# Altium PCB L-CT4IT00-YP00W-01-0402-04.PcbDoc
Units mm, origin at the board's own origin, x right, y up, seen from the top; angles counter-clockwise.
Board outline 187.63 x 116.13 mm, 6 copper layers (Top Layer, (Inserted) GND1, (Inserted) Signal3, (Inserted) Siganl4, (Inserted) GND5, Bottom Layer); 12 components, 0 nets, 14 pads, 0 vias.
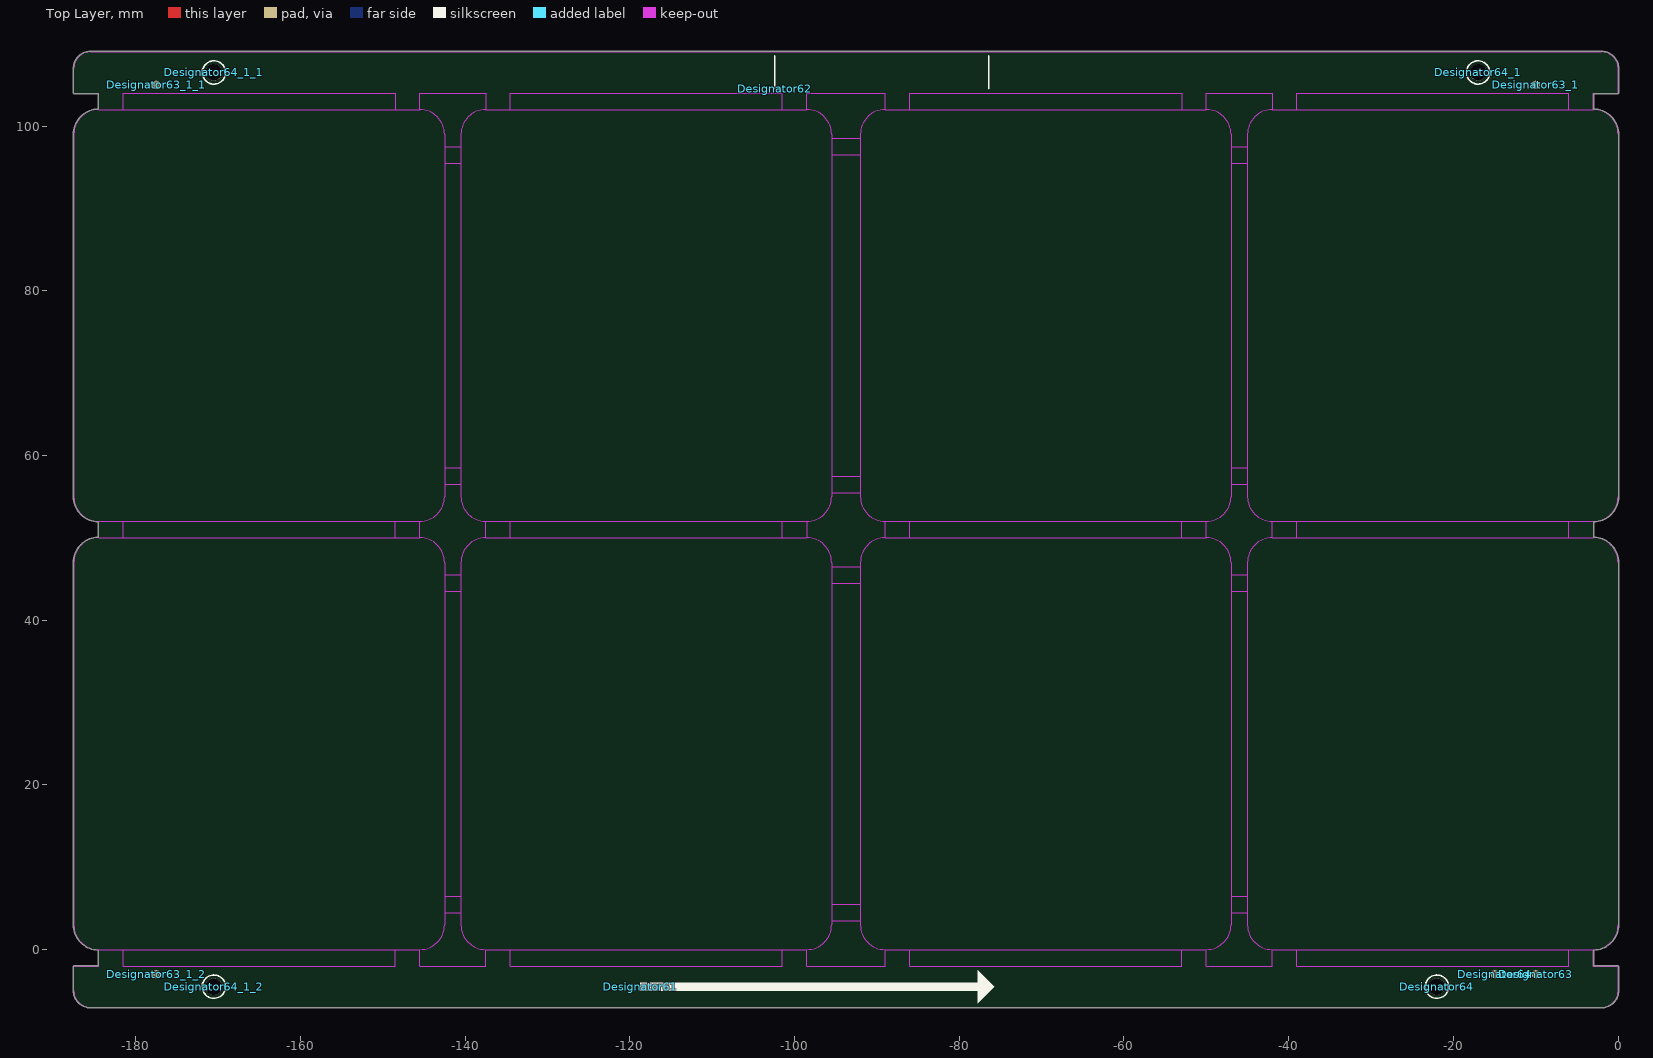
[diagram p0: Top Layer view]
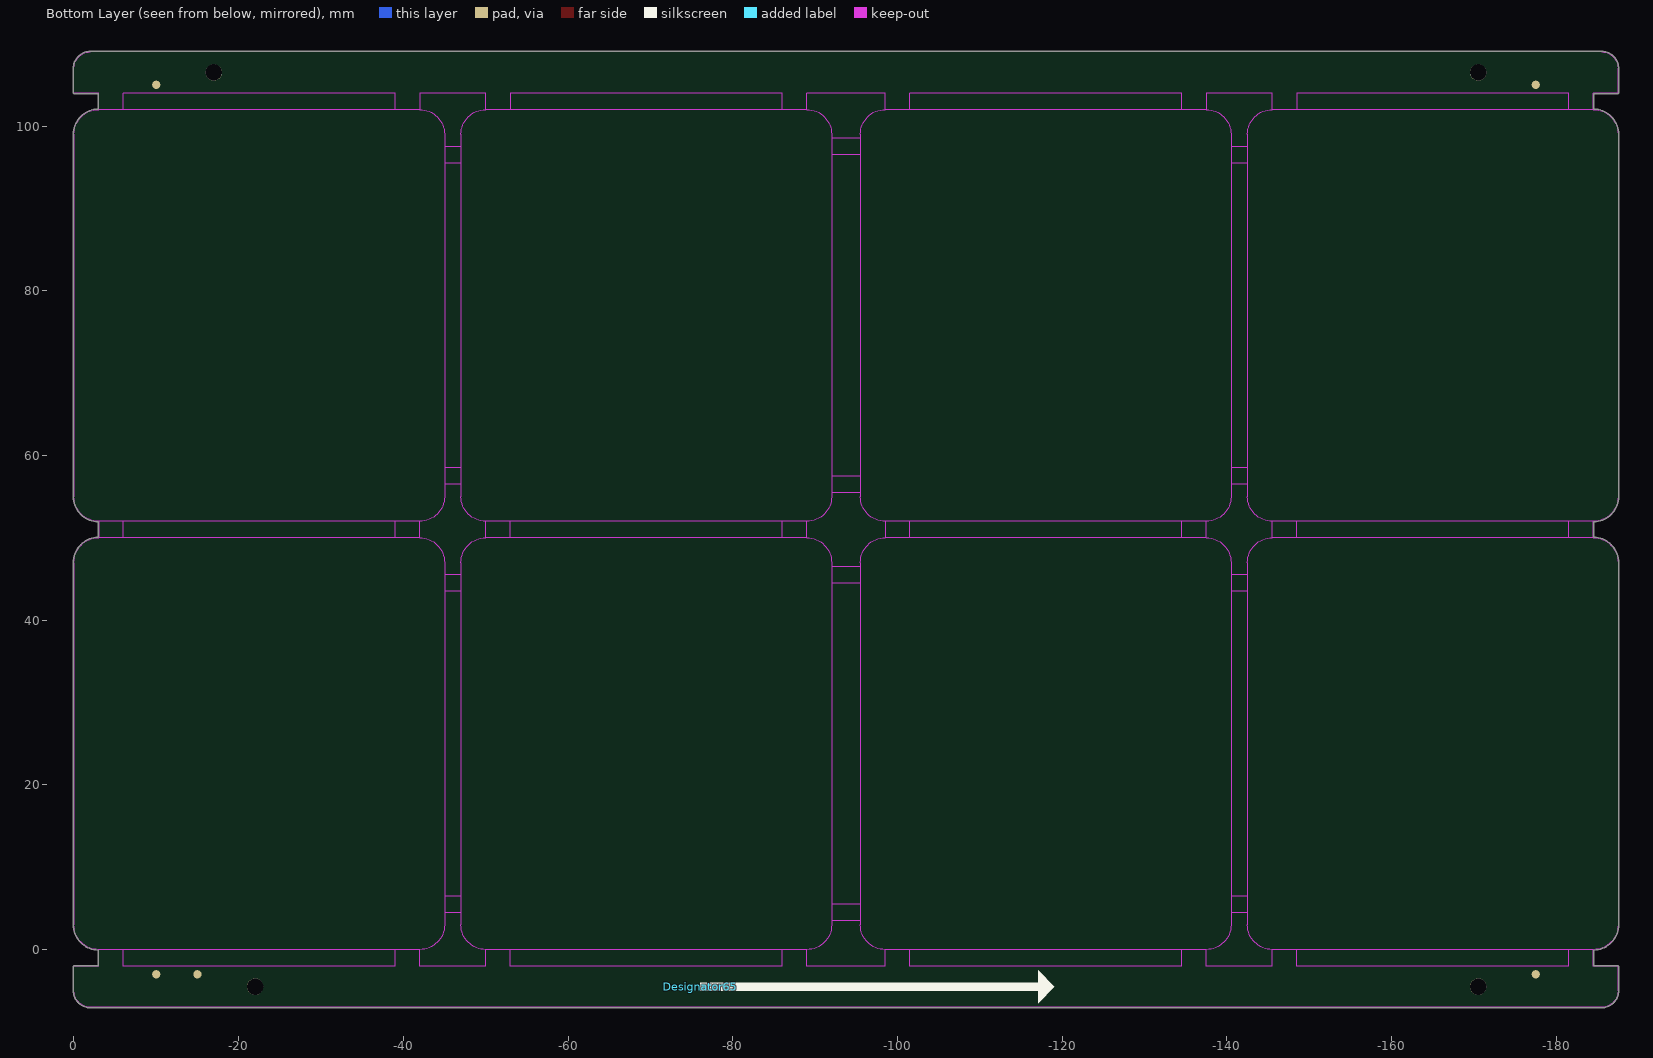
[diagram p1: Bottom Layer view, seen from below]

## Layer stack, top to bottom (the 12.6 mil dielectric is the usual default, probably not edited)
Top Solder: solder mask 0.0102, Solder Resist, Dk 3.5
Top Layer: signal copper 0.0356
(Inserted) Dielectric 5: prepreg 0.32, FR-4, Dk 4.8
(Inserted) GND1: signal copper 0.0356
(Inserted) Dielectric 4: prepreg 0.32, FR-4, Dk 4.8
(Inserted) Signal3: signal copper 0.0356
(Inserted) Dielectric 3: prepreg 0.32, FR-4, Dk 4.8
(Inserted) Siganl4: signal copper 0.0356
(Inserted) Dielectric 2: prepreg 0.32, FR-4, Dk 4.8
(Inserted) GND5: signal copper 0.0356
Dielectric 1: dielectric 0.32, FR-4, Dk 4.8
Bottom Layer: signal copper 0.0356
Bottom Solder: solder mask 0.0102, Solder Resist, Dk 3.5

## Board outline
-187.564,-5 -187.564,-2 -187.5,-1.936 -184.564,-1.936 -184.564,-0.063 cw(c-184.5,3) -187.564,3 -187.564,47 cw(c-184.5,47) -184.564,50.063 -184.564,51.937 cw(c-184.5,55) -187.564,55 -187.564,99 cw(c-184.5,99) -184.564,102.063 -184.564,103.936 -187.5,103.936 -187.564,104 -187.564,107 cw(c-185.5,107) -185.5,109.064 -2,109.064 cw(c-2,107) 0.064,107 0.064,104 0,103.936 -2.936,103.936 -2.936,102.063 cw(c-3,99) 0.064,99 0.064,98.999 0.064,55 cw(c-3,55) -2.936,51.937 -2.936,50.063 cw(c-3,47) 0.064,47 0.064,46.999 0.064,3 cw(c-3,3) -2.936,-0.063 -2.936,-1.936 0,-1.936 0.064,-2 0.064,-5 cw(c-2,-5) -2,-7.064 -185.5,-7.064 cw(c-185.5,-5)

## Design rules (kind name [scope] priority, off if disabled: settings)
Clearance [All] p1: gap=0.254 ignorepadtopadclearanceinfootprint=FALSE except(0: Arc-Hole Track-Hole SMDPad-Hole THPad-Hole Via-Hole Fill-Hole Poly-Hole Region-Hole Text-Hole)
PolygonConnect [All] p1: connectstyle=Relief reliefconductorwidth=0.254 reliefentries=4 polygonreliefangle="90 Angle" airgapwidth=0.254
RoutingVias [All] p1: holewidth=0.711 width=1.27 viastyle="Through Hole" minholewidth=0.711 minwidth=1.27 maxholewidth=0.711 maxwidth=1.27
SolderMaskExpansion [All] p1: expansion=0.102 istentingtop=FALSE
Width [All] p1: maxlimit=0.254 minlimit=0.254 preferedwidth=0.254
30 further rules are at their usual default settings.

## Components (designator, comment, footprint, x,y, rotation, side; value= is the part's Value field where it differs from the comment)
Designator61 "Comment" Arrow -118.75,-4.5 r0 top
Designator62 "Comment" "White oil-26X4" -102.4,104.55 r180 top
Designator63 "Comment" MARK -10,-3 r0 top
Designator63_1 "Comment" MARK -10,105 r0 top
Designator63_1_1 "Comment" MARK -177.5,105 r180 top
Designator63_1_2 "Comment" MARK -177.5,-3 r180 top
Designator64 "Comment" MARK -15,-3 r0 top
Designator64 "Comment" Toolinghole -22,-4.5 r0 top
Designator64_1 "Comment" Toolinghole -17,106.5 r0 top
Designator64_1_1 "Comment" Toolinghole -170.5,106.5 r180 top
Designator64_1_2 "Comment" Toolinghole -170.5,-4.5 r180 top
Designator65 "Comment" Arrow -76.064,-4.5 r180 bottom

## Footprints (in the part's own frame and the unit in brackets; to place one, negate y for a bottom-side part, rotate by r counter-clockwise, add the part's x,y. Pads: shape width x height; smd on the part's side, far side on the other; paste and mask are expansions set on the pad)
Arrow [mm] "方向箭头"
  silkscreen extent 0,-2 43,2
MARK [mm]
  round 1 smd mask+0.5: 1(0,0)
  round 1 smd far side mask+0.5: 2(0,0)
  Top Layer pour cut-out: -1.5,0 -1.386,-0.574 -1.061,-1.061 -0.574,-1.386 0,-1.5 0,-1.5 0.574,-1.386 1.061,-1.061 1.386,-0.574 1.5,0 1.5,0 1.386,0.574 1.061,1.061 0.574,1.386 0,1.5 0,1.5 -0.574,1.386 -1.061,1.061 -1.386,0.574 -1.5,0
  Bottom Layer pour cut-out: -1.5,0 -1.386,-0.574 -1.061,-1.061 -0.574,-1.386 0,-1.5 0,-1.5 0.574,-1.386 1.061,-1.061 1.386,-0.574 1.5,0 1.5,0 1.386,0.574 1.061,1.061 0.574,1.386 0,1.5 0,1.5 -0.574,1.386 -1.061,1.061 -1.386,0.574 -1.5,0
Toolinghole [mm]
  round 2 hole 2 unplated: 1(0,0)
  silkscreen extent -1.41,-1.41 1.41,1.41
"White oil-26X4" [mm] "二维码白油框"
  silkscreen extent -26,-4 0,0

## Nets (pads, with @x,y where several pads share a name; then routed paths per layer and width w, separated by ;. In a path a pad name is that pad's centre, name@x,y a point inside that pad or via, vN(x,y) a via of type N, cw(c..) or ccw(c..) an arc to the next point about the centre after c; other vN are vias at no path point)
pads on no net: Designator63.1 Designator63.2 Designator63_1.1 Designator63_1.2 Designator63_1_1.1 Designator63_1_1.2 Designator63_1_2.1 Designator63_1_2.2 Designator64.1 Designator64.2 Designator64_1.1 Designator64_1_1.1 Designator64_1_2.1

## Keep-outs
Keep-Out Layer:
  lines w0.127: -181.5,0 -181.5,-2 -148.5,-2 -148.5,0 ; -181.5,50 -181.5,52 ; -181.5,102 -181.5,104 -148.5,104 -148.5,102 ; -148.5,50 -148.5,52 ; -142.5,4.5 -140.5,4.5 ; -142.5,6.5 -140.5,6.5 ; -142.5,43.5 -140.5,43.5 ; -142.5,45.5 -140.5,45.5 ; -142.5,56.5 -140.5,56.5 ; -142.5,58.5 -140.5,58.5 ; -142.5,95.5 -140.5,95.5 ; -142.5,97.5 -140.5,97.5 ; -134.5,0 -134.5,-2 -101.5,-2 -101.5,0 ; -134.5,50 -134.5,52 ; -134.5,102 -134.5,104 -101.5,104 -101.5,102 ; -101.5,50 -101.5,52 ; -95.5,3.5 -92,3.5 ; -95.5,5.5 -92,5.5 ; -95.5,44.5 -92,44.5 ; -95.5,46.5 -92,46.5 ; -95.5,55.5 -92,55.5 ; -95.5,57.5 -92,57.5 ; -95.5,96.5 -92,96.5 ; -95.5,98.5 -92,98.5 ; -86,0 -86,-2 -53,-2 -53,0 ; -86,50 -86,52 ; -86,102 -86,104 -53,104 -53,102 ; -53,50 -53,52 ; -47,4.5 -45,4.5 ; -47,6.5 -45,6.5 ; -47,43.5 -45,43.5 ; -47,45.5 -45,45.5 ; -47,56.5 -45,56.5 ; -47,58.5 -45,58.5 ; -47,95.5 -45,95.5 ; -47,97.5 -45,97.5 ; -39,0 -39,-2 -6,-2 -6,0 ; -39,50 -39,52 ; -39,102 -39,104 -6,104 -6,102 ; -6,50 -6,52 ; -184.5,0 cw(c-184.5,3) -187.5,3 -187.5,47 cw(c-184.5,47) -184.5,50 ; -184.5,0 -184.5,-2 -187.5,-2 -187.5,-5 ccw(c-185.5,-5) -185.5,-7 -2,-7 ccw(c-2,-5) 0,-5 0,-2 -3,-2 -3,0 ; -184.5,0 -145.5,0 ; -184.5,50 -184.5,52 ; -184.5,50 -145.5,50 ; -184.5,52 cw(c-184.5,55) -187.5,55 -187.5,99 cw(c-184.5,99) -184.5,102 ; -184.5,52 -145.5,52 ; -184.5,102 -184.5,104 -187.5,104 -187.5,107 cw(c-185.5,107) -185.5,109 -2,109 cw(c-2,107) 0,107 0,104 -3,104 -3,102 ; -184.5,102 -145.5,102 ; -145.5,0 ccw(c-145.5,3) -142.5,3 -142.5,47 ccw(c-145.5,47) -145.5,50 ; -145.5,0 -145.5,-2 -137.5,-2 -137.5,0 ; -145.5,50 -145.5,52 ; -145.5,52 ccw(c-145.5,55) -142.5,55 -142.5,99 ccw(c-145.5,99) -145.5,102 ; -145.5,102 -145.5,104 -137.5,104 -137.5,102 ; -137.5,0 cw(c-137.5,3) -140.5,3 -140.5,47 cw(c-137.5,47) -137.5,50 ; -137.5,0 -98.5,0 ; -137.5,50 -137.5,52 ; -137.5,50 -98.5,50 ; -137.5,52 cw(c-137.5,55) -140.5,55 -140.5,99 cw(c-137.5,99) -137.5,102 ; -137.5,52 -98.5,52 ; -137.5,102 -98.5,102 ; -98.5,0 ccw(c-98.5,3) -95.5,3 -95.5,47 ccw(c-98.5,47) -98.5,50 ; -98.5,0 -98.5,-2 -89,-2 -89,0 ; -98.5,50 -98.5,52 ; -98.5,52 ccw(c-98.5,55) -95.5,55 -95.5,99 ccw(c-98.5,99) -98.5,102 ; -98.5,102 -98.5,104 -89,104 -89,102 ; -89,0 cw(c-89,3) -92,3 -92,47 cw(c-89,47) -89,50 ; -89,0 -50,0 ; -89,50 -89,52 ; -89,50 -50,50 ; -89,52 cw(c-89,55) -92,55 -92,99 cw(c-89,99) -89,102 ; -89,52 -50,52 ; -89,102 -50,102 ; -50,0 ccw(c-50,3) -47,3 -47,47 ccw(c-50,47) -50,50 ; -50,0 -50,-2 -42,-2 -42,0 ; -50,50 -50,52 ; -50,52 ccw(c-50,55) -47,55 -47,99 ccw(c-50,99) -50,102 ; -50,102 -50,104 -42,104 -42,102 ; -42,0 cw(c-42,3) -45,3 -45,47 cw(c-42,47) -42,50 ; -42,0 -3,0 ; -42,50 -42,52 ; -42,50 -3,50 ; -42,52 cw(c-42,55) -45,55 -45,99 cw(c-42,99) -42,102 ; -42,52 -3,52 ; -42,102 -3,102 ; -3,0 ccw(c-3,3) 0,3 0,47 ccw(c-3,47) -3,50 ; -3,50 -3,52 ; -3,52 ccw(c-3,55) 0,55 0,99 ccw(c-3,99) -3,102

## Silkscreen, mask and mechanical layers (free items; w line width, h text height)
Top Solder:
  rectangle: -6,-2 -3,0
  rectangle: -148.5,-2 -145.5,0
  region: -181.5,0 -184.5,0 -184.5,-2 -181.5,-2
  region: -181.5,52 -184.5,52 -184.5,50 -181.5,50
  rectangle: -148.5,50 -145.5,52
  region: -134.5,52 -137.5,52 -137.5,50 -134.5,50
  rectangle: -101.5,50 -98.5,52
  rectangle: -101.5,102 -98.5,104
  region: -134.5,104 -137.5,104 -137.5,102 -134.5,102
  region: -39,104 -42,104 -42,102 -39,102
  rectangle: -6,102 -3,104
  rectangle: -6,50 -3,52
  region: -39,52 -42,52 -42,50 -39,50
  rectangle: -53,50 -50,52
  region: -86,52 -89,52 -89,50 -86,50
  region: -86,0 -89,0 -89,-2 -86,-2
  rectangle: -53,-2 -50,0
  rectangle: -101.5,-2 -98.5,0
  region: -134.5,0 -137.5,0 -137.5,-2 -134.5,-2
  region: -181.5,104 -184.5,104 -184.5,102 -181.5,102
  rectangle: -148.5,102 -145.5,104
  region: -86,104 -89,104 -89,102 -86,102
  rectangle: -53,102 -50,104
  region: -39,0 -42,0 -42,-2 -39,-2
  region: -92,44.5 -92,46.5 -95.482,46.5 -95.482,44.5
  region: -95.482,57.5 -95.482,55.5 -92,55.5 -92,57.5
  region: -92,96.5 -92,98.5 -95.482,98.5 -95.482,96.5
  region: -95.482,5.5 -95.482,3.5 -92,3.5 -92,5.5
  region: -142.5,58.5 -142.5,56.5 -140.5,56.5 -140.5,58.5
  region: -140.5,95.5 -140.5,97.5 -142.5,97.5 -142.5,95.5
  region: -140.5,43.5 -140.5,45.5 -142.5,45.5 -142.5,43.5
  region: -142.5,6.5 -142.5,4.5 -140.5,4.5 -140.5,6.5
  region: -47,6.5 -47,4.5 -45,4.5 -45,6.5
  region: -45,43.5 -45,45.5 -47,45.5 -47,43.5
  region: -45,95.5 -45,97.5 -47,97.5 -47,95.5
  region: -47,58.5 -47,56.5 -45,56.5 -45,58.5
Bottom Solder:
  rectangle: -6,-2 -3,0
  rectangle: -148.5,-2 -145.5,0
  region: -181.5,0 -184.5,0 -184.5,-2 -181.5,-2
  region: -181.5,52 -184.5,52 -184.5,50 -181.5,50
  rectangle: -148.5,50 -145.5,52
  region: -134.5,52 -137.5,52 -137.5,50 -134.5,50
  rectangle: -101.5,50 -98.5,52
  rectangle: -101.5,102 -98.5,104
  region: -134.5,104 -137.5,104 -137.5,102 -134.5,102
  region: -39,104 -42,104 -42,102 -39,102
  rectangle: -6,102 -3,104
  rectangle: -6,50 -3,52
  region: -39,52 -42,52 -42,50 -39,50
  rectangle: -53,50 -50,52
  region: -86,52 -89,52 -89,50 -86,50
  region: -86,0 -89,0 -89,-2 -86,-2
  rectangle: -53,-2 -50,0
  region: -92,44.5 -92,46.5 -95.482,46.5 -95.482,44.5
  rectangle: -101.5,-2 -98.5,0
  region: -134.5,0 -137.5,0 -137.5,-2 -134.5,-2
  region: -181.5,104 -184.5,104 -184.5,102 -181.5,102
  rectangle: -148.5,102 -145.5,104
  region: -86,104 -89,104 -89,102 -86,102
  rectangle: -53,102 -50,104
  region: -39,0 -42,0 -42,-2 -39,-2
  region: -95.482,57.5 -95.482,55.5 -92,55.5 -92,57.5
  region: -92,96.5 -92,98.5 -95.482,98.5 -95.482,96.5
  region: -95.482,5.5 -95.482,3.5 -92,3.5 -92,5.5
  region: -142.5,58.5 -142.5,56.5 -140.5,56.5 -140.5,58.5
  region: -140.5,95.5 -140.5,97.5 -142.5,97.5 -142.5,95.5
  region: -140.5,43.5 -140.5,45.5 -142.5,45.5 -142.5,43.5
  region: -142.5,6.5 -142.5,4.5 -140.5,4.5 -140.5,6.5
  region: -47,6.5 -47,4.5 -45,4.5 -45,6.5
  region: -45,43.5 -45,45.5 -47,45.5 -47,43.5
  region: -45,95.5 -45,97.5 -47,97.5 -47,95.5
  region: -47,58.5 -47,56.5 -45,56.5 -45,58.5
Mechanical 1:
  lines w0.127: -142.5,-2 -142.5,0 ; -140.5,104 -140.5,102 ; -47,-2 -47,0 ; -45,104 -45,102 ; -142.5,0 -142.5,50 ; -142.5,0 -187.5,0 -187.5,50 -142.5,50 ; -142.5,0 -140.5,0 ; -142.5,50 -142.5,52 ; -142.5,52 -187.5,52 -187.5,102 -142.5,102 ; -142.5,52 -142.5,102 ; -142.5,102 -140.5,102 ; -140.5,0 -95.5,0 ; -140.5,0 -140.5,50 ; -140.5,50 -95.5,50 -95.5,0 ; -140.5,50 -140.5,52 ; -140.5,52 -140.5,102 ; -140.5,52 -95.5,52 -95.5,102 -140.5,102 ; -95.5,0 -92,0 ; -92,0 -47,0 ; -92,0 -92,50 -47,50 ; -47,0 -45,0 ; -47,0 -47,50 ; -47,50 -47,52 ; -47,52 -47,102 ; -47,52 -92,52 -92,102 -47,102 ; -47,102 -45,102 ; -45,0 -45,50 ; -45,0 0,0 0,50 -45,50 ; -45,50 -45,52 ; -45,52 0,52 0,102 -45,102 ; -45,52 -45,102

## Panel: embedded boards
"L-CT4IT00-YP00W-01_V04.PcbDoc" at -142.5,52, 1 rows x 1 columns, spacing 63.5 x 38.1, rotation 0
"L-CT4IT00-YP00W-01_V04.PcbDoc" at -142.5,0, 1 rows x 1 columns, spacing 63.5 x 38.1, rotation 0
"L-CT4IT00-YP00W-01_V04.PcbDoc" at -140.5,50, 1 rows x 1 columns, spacing 63.5 x 38.1, rotation 180
"L-CT4IT00-YP00W-01_V04.PcbDoc" at -140.5,102, 1 rows x 1 columns, spacing 63.5 x 38.1, rotation 180
"L-CT4IT00-YP00W-01_V04.PcbDoc" at -47,0, 1 rows x 1 columns, spacing 63.5 x 38.1, rotation 0
"L-CT4IT00-YP00W-01_V04.PcbDoc" at -47,52, 1 rows x 1 columns, spacing 63.5 x 38.1, rotation 0
"L-CT4IT00-YP00W-01_V04.PcbDoc" at -45,102, 1 rows x 1 columns, spacing 63.5 x 38.1, rotation 180
"L-CT4IT00-YP00W-01_V04.PcbDoc" at -45,50, 1 rows x 1 columns, spacing 63.5 x 38.1, rotation 180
